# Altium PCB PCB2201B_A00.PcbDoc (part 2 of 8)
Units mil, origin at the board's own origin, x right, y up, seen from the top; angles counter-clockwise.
Board outline 4523.63 x 2358.23 mil, 6 copper layers (Top Layer, Signal Layer 2, Signal Layer 3, Signal Layer 4, Signal Layer 5, Bottom Layer), stack 61.221 mil thick; 383 components, 308 nets, 1386 pads, 1147 vias.
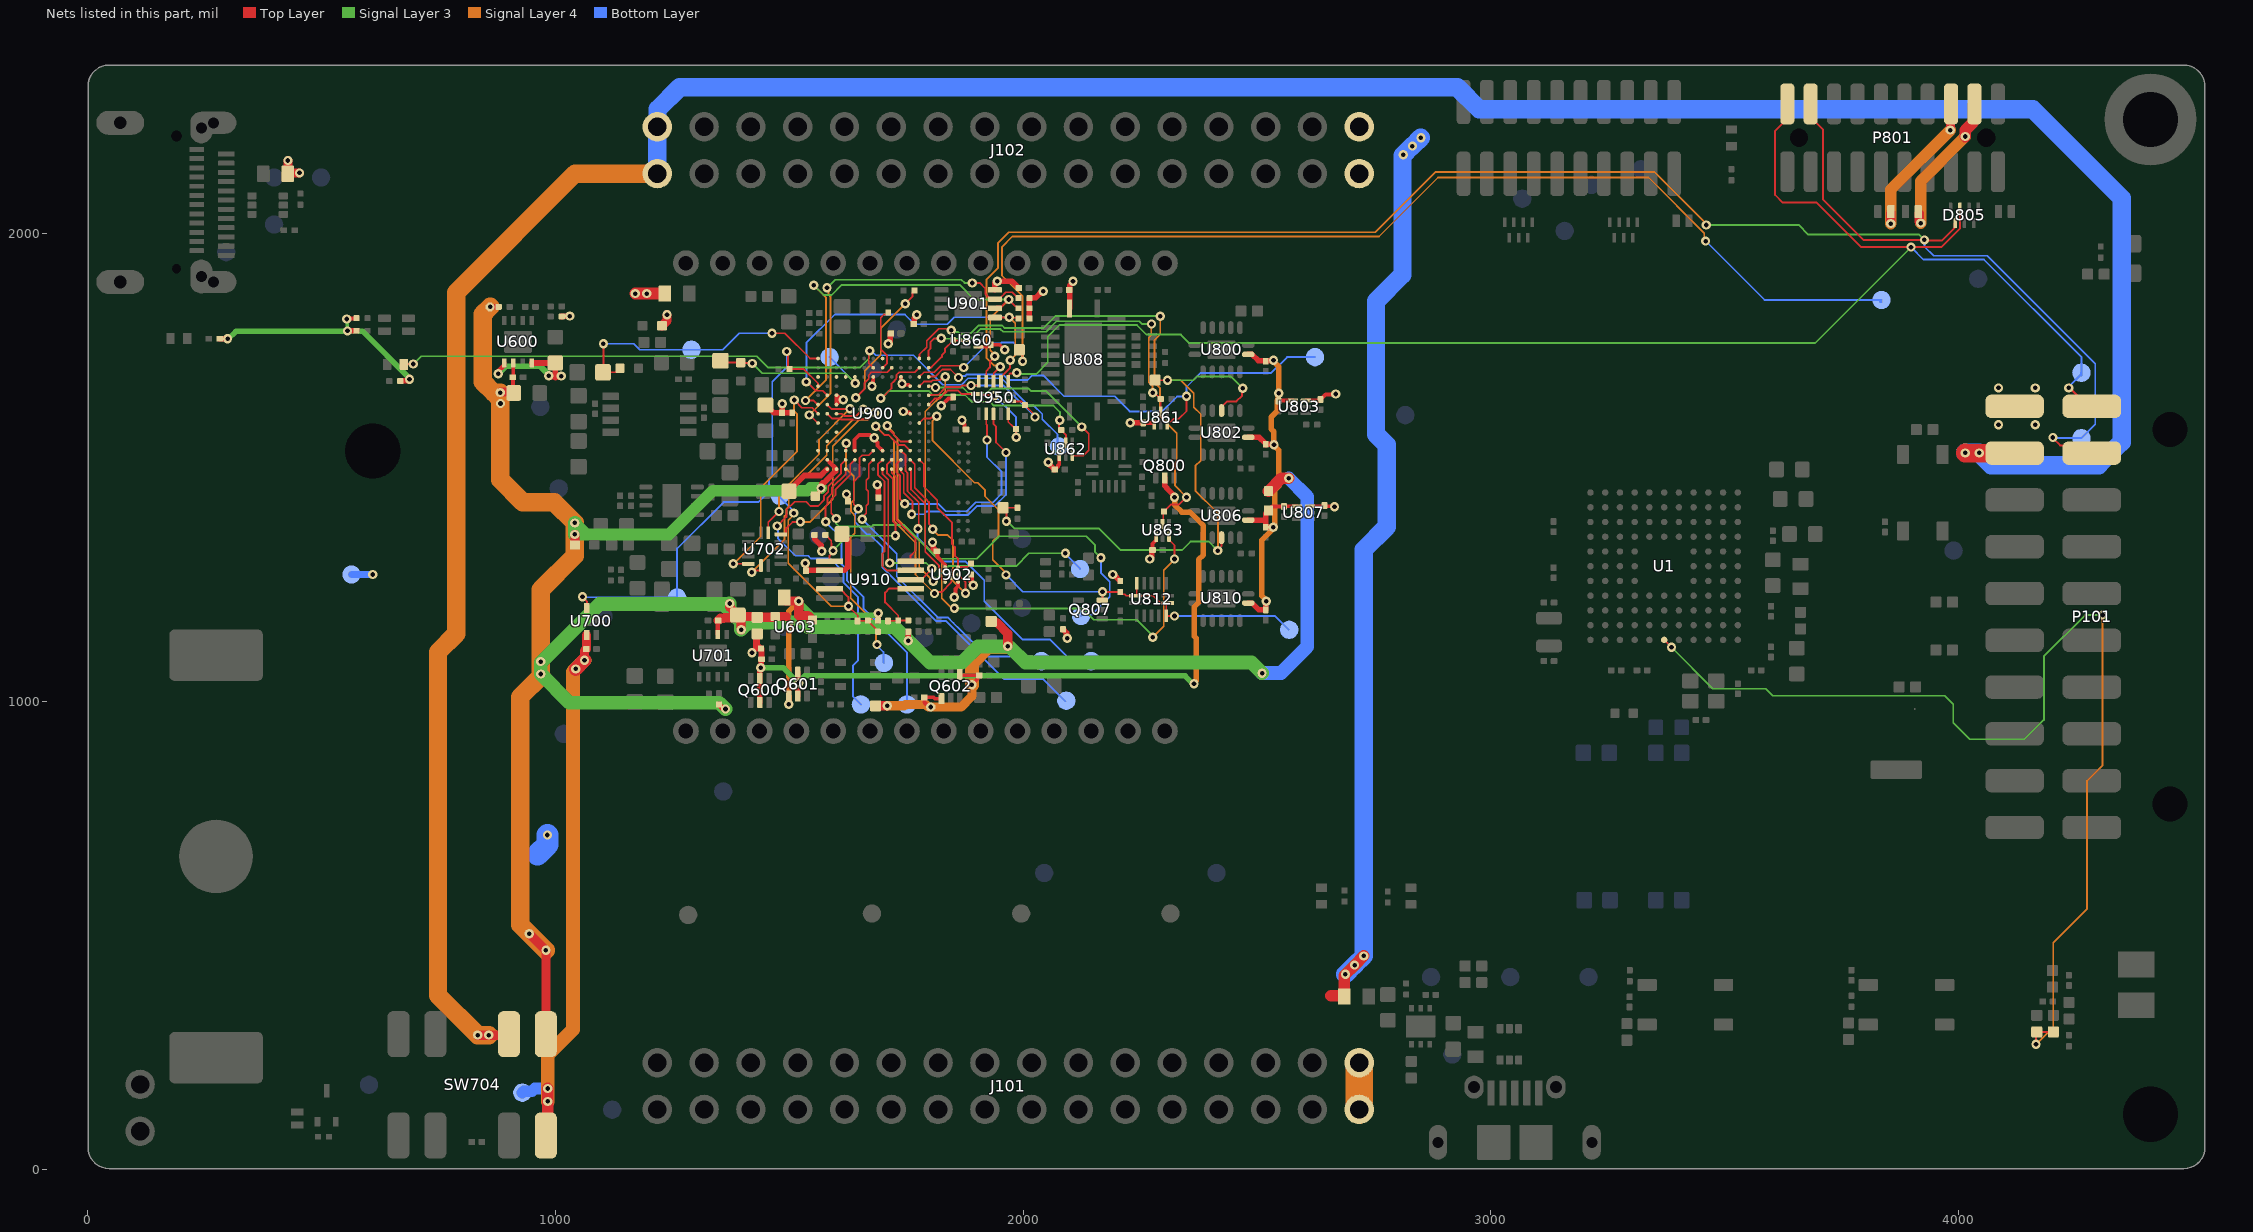
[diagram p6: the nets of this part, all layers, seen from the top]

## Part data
LED100 LED101: library part Yellow

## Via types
v1: diameter 19.68, hole 9.84, Top Layer to Bottom Layer, tented both sides, 768 vias
v2: diameter 20, hole 9.84, Top Layer to Bottom Layer, tented both sides, 379 vias

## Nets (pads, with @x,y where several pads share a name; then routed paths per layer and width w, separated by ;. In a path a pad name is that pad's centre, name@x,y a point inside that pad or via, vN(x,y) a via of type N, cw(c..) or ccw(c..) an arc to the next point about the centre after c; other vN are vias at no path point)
3V3: C607.1 C807.1 C808.1 C860.1 C862.1 C864.1 C866.1 C868.1 C907.1 C908.1 C909.1 C910.1 C911.1 C914.1 C921.1 C922.1 C924.1 C925.1 C926.1 C927.1 C951.1 D807.1 J101.31 J101.32 J102.31 J102.32 L704.1 L900.1 P101.20 P801.3 R601.2 R838.2 R840.2 R903.1 R906.2 R907.1 R908.1 R909.1 R912.1 R919.1 R920.1 R982.1 TPJ600.1 TPJ950.1 U600.1 U600.4 U803.6 U807.6 U808.1 U860.1 U861.1 U862.1 U863.1 U900.C6 U900.C9 U900.G3 U900.H11 U900.J11 U900.K3 U900.L4 U900.L7 U901.8 U902.A1 U902.E3 U910.2 | length 2868.1
  Top Layer w7.87: v1(555.02,1817.7) 555.92,1818.59 574.77,1818.59 R920.1@575.67,1819.49 ; v2@1606.3,1644.69 1606.3,1639.76 U900.H11@1601.38,1634.84 U900.J11@1601.38,1654.53 1603.17,1654.53 1612.54,1645.16 v2(1615.82,1645.16) ; U900.C9@1640.75,1536.42 1640.04,1537.12 1640.04,1559.39 1650.26,1569.6 1673.18,1569.6 1677.82,1564.96 v2@1682.09,1564.96 ; v2(1677.17,1674.21) 1679.49,1676.53 1679.49,1685.11 1680.12,1685.74 U900.L7@1680.12,1693.9 ; v2(1682.09,1563.98) 1682.09,1560.7 1689.15,1553.63 1689.15,1547.07 U900.C6@1699.8,1536.42 ; v2(1712.35,1764.79) v2@1714.67,1767.11 ; U900.L4@1739.17,1693.9 1739.17,1681.84 v2(1741.45,1679.56) ; v2(1744.09,1620.08) 1746.41,1617.76 1756.26,1617.76 U900.G3@1758.86,1615.16 ; v2@1744.09,1679.13 1745.99,1677.24 1755.83,1677.24 U900.K3@1758.86,1674.21 ; C914.1@1816.08,1321.44 1817.09,1320.43 1817.09,1309.03 1833.59,1292.53 1833.59,1287.48 U902.A1@1833.66,1287.4 ; v2(1825.03,1632.09) 1840.77,1647.83 1848.45,1647.83 1850.82,1650.2 C911.1@1850.82,1650.98 ; v2(1853.33,1223.18) 1855.67,1223.18 1855.67,1240.84 1861.15,1246.32 1861.15,1255.83 U902.E3@1861.22,1255.91 ; v2(1869.52,1600.95) 1869.52,1597.67 1875,1592.19 1875,1584.09 1877.36,1581.73 C909.1@1878.15,1581.73 ; U860.1@1904.49,1758.23 1927.32,1758.23 1931.1,1762.01 C862.1@1931.1,1762.8 1950.37,1762.8 1960.83,1752.34 v2(1961.04,1752.34) ; C860.1@2067.91,1496.06 2068.7,1496.06 2074.61,1501.97 2074.61,1504.7 2077.76,1507.85 U862.1@2077.76,1525.59 ; C864.1@2256.89,1595.47 2280.51,1595.47 U861.1@2280.51,1592.52 ; C866.1@2276.57,1323.82 2276.57,1337.6 2284.45,1345.47 U863.1@2284.45,1352.36 ; U803.6@2604.33,1643.7 2633.86,1643.7 C807.1@2635.83,1645.67 2635.83,1646.46 2638.19,1648.82 2638.98,1648.82 2646.65,1656.5 2667.32,1656.5 v1(2668.31,1657.48) ; U807.6@2613.38,1417.7 2642.76,1417.7 C868.1@2644.17,1419.1 2645.41,1417.86 2664.38,1417.86 v1(2665.63,1416.61)
  Top Layer w10: v1(878.46,1700.72) 880.31,1702.57 880.31,1707.99 891.2,1718.87 U600.1@891.2,1723.64
  Top Layer w11.81: C907.1@1449.8,1629.92 1454.72,1629.92 1467.52,1617.13 C924.1@1485.24,1617.13 ; v2(1485.24,1636.81) C924.1@1485.24,1617.13 ; C925.1@1506.89,1617.13 C924.1@1485.24,1617.13 ; v2(1535,1295.63) 1536.02,1294.61 1536.02,1279.92 C922.1@1536.42,1279.53 ; C922.1@1536.42,1280.12 1536.81,1280.51 1618.08,1280.51 1625,1287.43 1625,1345.47 C921.1@1614.17,1356.3 ; R982.1@1553.98,1356.38 1554.37,1356.38 1554.76,1355.98 1554.76,1347.68 1568.38,1334.06 1568.38,1322.89 v2(1569.95,1321.32) ; v2(1688.55,1463.74) 1688.27,1463.74 1688.27,1463.06 1690.55,1460.78 C926.1@1690.55,1435.16 ; v2@1712.6,1764.79 v2(1712.35,1764.79) 1712.35,1767.01 1716.42,1771.07 1716.42,1786.14 1716.81,1786.54 C910.1@1717.6,1786.54 ; C908.1@1767.28,1807.09 1767.68,1807.48 1767.68,1819.32 1772.72,1824.36 v2(1772.72,1826.57) ; v2(1806.53,1340.55) 1806.1,1340.55 1806.1,1338.34 v2@1807.87,1336.56 ; R906.2@1888.75,1271.56 1889.14,1271.17 1889.14,1255.96 1893.8,1251.29 v2(1893.8,1249.08) ; U901.8@1939.96,1879.92 1939.96,1893.7 v2(1944.88,1898.62) 1976.38,1898.62 C951.1@1991.14,1883.86 ; R908.1@2013.78,1818.9 R907.1@2013.78,1840.55 R909.1@2013.78,1862.2 2014.17,1862.6 2026.72,1862.6 2041.09,1876.97 v2(2043.31,1876.97) ; v2(2054.13,1511.81) 2055.7,1510.24 2055.7,1506.31 2057.2,1504.81 2058.38,1504.81 2067.13,1496.06 C860.1@2067.91,1496.06 ; R838.2@2085.63,1154.53 2086.02,1154.13 2086.02,1153.74 2092.92,1146.84 2092.92,1137.39 v2(2094.49,1135.83) ; U808.1@2099.41,1840.35 2099.41,1878.94 C808.1@2098.43,1879.92 2099.21,1879.92 2099.61,1880.32 2099.61,1889.29 2106.72,1896.41 v2(2106.72,1898.62) ; v2(2191.93,1271.65) 2193.5,1270.09 2195.86,1270.09 2207.68,1258.27 R840.2@2207.68,1257.87 ; v2(2228.95,1595.93) 2229.18,1595.7 2256.66,1595.7 C864.1@2256.89,1595.47 ; v2(2270.67,1304.84) 2270.67,1305.37 2275.39,1310.09 2275.39,1323.43 2275.79,1323.82 C866.1@2276.57,1323.82
  Top Layer w12: R903.1@283.46,1775.59 v1(300.2,1775.59) ; v1(556.42,1792.17) 556.61,1792.36 575.47,1792.36 R919.1@575.67,1792.56 ; R912.1@669.29,1685.04 669.59,1685.34 683.26,1685.34 686.9,1688.98 v1(688.98,1688.98) ; U600.4@950.26,1723.64 995.29,1723.64 C607.1@996.06,1724.41 ; v1(986.47,1696.4) 987.94,1694.93 998.69,1694.93 1000.45,1693.17 ; C607.1@999.47,1723.64 C607.1@1000.45,1723.64 ; 1000.98,1692.64 1000.45,1693.17 ; C607.1@1001.44,1723.64 C607.1@1000.45,1723.64 ; v1(1013.4,1695.69) 1011.93,1694.22 1001.51,1694.22 1000.45,1693.17 ; R601.2@1014.23,1823.05 1014.53,1823.35 1031.02,1823.35 v1(1031.5,1823.82) ; v2(1622.84,1443.25) 1622.84,1441.09 1625.69,1438.25 1625.69,1428.45 C927.1@1625.98,1428.15 ; v2(1806.53,1340.55) 1808.06,1339.02 1808.06,1328.67 1815.29,1321.44 C914.1@1816.08,1321.44 ; 1000.45,1693.17 C607.1@1000.45,1723.64
  Top Layer w19.68: L704.1@1228.35,1803.15 1239.17,1813.98 v2(1239.17,1826.77) ; D807.1@3915.35,2043.31 3915.35,2025.59 v1(3918.31,2022.64)
  Top Layer w25: v2(1171.26,1872.05) v2(1195.87,1872.05) L900.1@1234.65,1872.05 ; v2(4013.78,2207.68) 4013.78,2221.22 4030.77,2238.21 4030.77,2274.72 P801.3@4033.27,2277.22
  Signal Layer 3 w4: J101.32@2718.5,225.39 J101.32@2722.44,229.33
  Signal Layer 3 w7.87: v1(555.02,1817.7) 555.72,1817 555.72,1792.86 v1(556.42,1792.17)
  Signal Layer 3 w12: v1@300.2,1773.62 300.31,1773.62 318.02,1791.34 556.42,1791.34 562.97,1791.34 562.57,1791.75 588.16,1791.75 690.93,1688.98 v1@691.93,1688.98 ; v1(878.46,1700.72) 894.48,1716.73 968.22,1716.73 986.47,1698.48 v1(986.47,1696.4)
  Signal Layer 4 w25: v1(3918.31,2022.64) 3918.31,2112.2 v2(4013.78,2207.68)
  Signal Layer 4 w59.06: J101.31@2718.5,128.43 J101.32@2718.5,225.39
  Bottom Layer w15.75: TPJ600.1@564.95,1271.71 610.18,1271.71 v1(610.24,1271.65)
  Bottom Layer w47.24: TPJ950.1@962.55,673.21 983.62,694.28 v1(983.62,715.04)
  other v1: 4084.54,1591.73 4163.28,1591.73 4084.54,1670.47 4163.28,1670.47
3V6_SW: C608.1 L702.1 Q601.1 R639.2 U603.B1 | length 565.5
  Top Layer w7.87: U603.B1@1520.67,1167.32 1520.67,1184.06
  Top Layer w11.81: Q601.1@1499.02,1011.81 v2(1499.09,994.64) v2(1499.09,994.64) ; R639.2@1689.96,1173.23 1690.35,1173.62 1690.35,1185.19 1691.73,1186.56 1690.29,1187.99 v2(1690.84,1188.54)
  Top Layer w19.68: L702.1@1489.76,1222.44 1489.76,1218.31 1493.11,1214.96 1520.19,1214.96 1520.58,1214.57 v2(1520.67,1214.57) 1520.67,1184.06 1540.35,1184.06 C608.1@1550.2,1174.21
  Signal Layer 3 w11.81: v2(1520.67,1214.57) 1550.9,1184.33 1685.07,1184.33 1689.51,1188.77 1690.29,1187.99 v2(1690.84,1188.54)
  Signal Layer 4 w11.81: v2(1499.09,994.64) 1499.09,1192.99 v2(1520.67,1214.57)
3V6_SW_SENSE: C641.1 R639.1 R640.2 TP923.1 U910.4 | length 490.3
  Top Layer w3.94: U910.4@1586.61,1241.14 1609.25,1241.14 1626.97,1223.43 v2(1626.97,1203.74) 1646.65,1184.06 C641.1@1646.65,1172.24 1647.15,1172.74 1667.82,1172.74 R640.2@1668.31,1173.23 1668.31,1172.83 1685.63,1155.51 1685.63,1153.94 R639.1@1689.96,1149.61
  Signal Layer 4 w3.94: v1(1509.84,1403) 1509.84,1398.83 1498.31,1387.3 1498.31,1295.98 1590.55,1203.74 v2(1626.97,1203.74)
  Bottom Layer w3.94: TP923.1@1480.31,1439.96 1480.31,1436.52 1510.83,1406 1510.83,1405.51 1510.83,1403.98 v1(1509.84,1403)
5V: C600.1 C609.1 C611.1 C673.1 C674.1 C702.1 C703.1 C901.1 D806.1 L402.1 L600.2 L700.1 L800.1 P801.5 Q602.1 Q602.4 R600.2 R622.2 R633.2 R681.2 R690.2 R700.2 SW704.8 U600.2 U603.A2 U603.B2 U701.2 U900.A11 U900.B12 | length 8753.4
  Top Layer w7.87: C611.1@909.45,1661.42 911.2,1659.66 C611.1@911.87,1659.66 ; C600.1@909.9,1693.13 909.9,1662.93 C611.1@911.42,1661.42 ; C600.1@910.43,1693.9 910.4,1693.93 910.4,1723.15 U600.2@910.89,1723.64 ; C702.1@1347.44,1172.24 C702.1@1348.43,1173.23 ; 1493.11,1182.09 1500.23,1174.96 1500.23,1172.33 1504.92,1167.64 U603.A2@1504.92,1151.57 ; C901.1@1556.1,1438.98 1565.96,1448.84 1565.96,1454.1 v2(1568.28,1456.42) ; U900.B12@1581.69,1516.73 1587.6,1510.83 1587.6,1509.84 ; C674.1@1791.57,1006.77 C674.1@1789.21,1009.13 ; v1(1802.68,988.62) 1799.49,988.62 1789.72,998.38 1789.27,998.38 C674.1@1789.21,1009.13 ; Q602.1@1825.4,1006.5 1811.23,1006.5 1808.59,1009.13 C674.1@1789.21,1009.13 C674.1@1789.21,1009.13 ; Q602.4@1865.16,1058.07 1866.97,1056.26 C673.1@1905.67,1056.26 ; v1(1890.75,1035.87) 1903.31,1048.43 1903.31,1053.9 C673.1@1905.67,1056.26 ; C673.1@1906.46,1056.26 C673.1@1905.67,1056.26
  Top Layer w9.84: U701.2@1347.44,1143.7 C702.1@1347.44,1172.24 ; 1587.6,1510.83 1599.41,1499.02 U900.A11@1599.41,1496.06
  Top Layer w11.81: v1(861.22,1843.5) 861.33,1843.61 879.29,1843.61 R600.2@879.39,1843.72 ; R700.2@1350.39,994.09 1350.39,993.7 1358.23,985.86 1362.56,985.86 v2(1364.13,984.3) ; 1581.39,1474.67 1581.59,1474.67 ; U900.A11@1599.41,1495.08 1599.41,1492.49 1581.59,1474.67 ; v2(1754.92,1129.92) R633.2@1754.92,1149.61 ; v2@1569.85,1460.2 1569.85,1465.36 1572.01,1467.52 1574.44,1467.52 1581.59,1474.67 ; v2@1569.85,1460.2 1569.85,1457.98 v2(1568.28,1456.42) 1568.28,1458.63 v2@1569.85,1460.2
  Top Layer w19.68: v1(429.13,2156.5) 429.13,2128.35 L600.2@428.74,2127.95 430.71,2129.92 v1(453.74,2129.92) ; v1(882.87,1660.43) 883.86,1661.42 C611.1@909.45,1661.42 ; v1(944.88,503.94) v1(980.31,468.5) SW704.8@980.31,289.37 SW704.8@980.31,285.43 ; L700.1@1042.32,1334.65 v2(1042.32,1357.28) ; C702.1@1348.43,1173.23 1353.35,1178.15 1360.54,1178.15 1361.52,1179.13 1384.84,1179.13 C703.1@1390.75,1185.04 ; v2(1373.03,1209.65) 1373.09,1209.59 1373.09,1201.71 1389.76,1185.04 C703.1@1390.75,1185.04 ; v2(1397.64,1153.54) 1397.58,1153.6 1397.58,1179.13 C703.1@1394.62,1182.09 ; 1493.11,1182.09 C609.1@1470.47,1182.09 1468.5,1180.12 R622.2@1432.09,1180.12 1430.12,1182.09 C703.1@1394.62,1182.09 ; R681.2@1685.04,991.14 v1(1709.65,991.14) ; R690.2@1932.09,1171.26 1934.06,1169.29 1943.5,1169.29 1967.46,1145.34 1967.46,1118.17 v2(1967.52,1118.11) ; v1(3854.33,2021.65) D806.1@3854.33,2044.54 ; v1(3981.3,2221.46) 3981.92,2222.08 3981.92,2275.88 P801.5@3983.27,2277.22 ; C703.1@1390.75,1185.04 1393.7,1182.09 C703.1@1394.62,1182.09 ; C703.1@1390.75,1185.04 1391.67,1185.04 C703.1@1394.62,1182.09
  Top Layer w25: L800.1@2524.61,1449.8 2552.17,1477.36 v2(2567.91,1477.36) ; 2658.19,371.34 2685.73,371.34 L402.1@2686.42,370.65 ; L402.1@2686.42,370.08 L402.1@2686.42,370.65 ; v1(2728.35,456.69) v1(2708.66,437.01) 2686.42,414.76 L402.1@2686.42,370.65
  Signal Layer 3 w25: v2(1042.32,1357.28) 1066.93,1357.28 ; v2(1042.32,1381.89) 1066.93,1357.28 ; v2(1568.28,1456.42) 1545.33,1456.42 1539.65,1450.73 1337.34,1450.73 1243.9,1357.28 1066.93,1357.28
  Signal Layer 3 w29.53: v2(1042.32,1357.28) v2(1042.32,1381.89) ; v2(1364.13,984.3) 1350.98,997.44 1031.1,997.44 v2(969.49,1059.06) 969.49,1083.66 1094.78,1208.96 1358.85,1208.96 ; v2@1373.03,1208.96 1358.85,1208.96 ; v2(1373.03,1209.65) 1373.03,1194.78 ; v2(1967.52,1118.11) 1903.54,1118.11 1869.09,1083.66 1801.18,1083.66 v2(1754.92,1129.92) 1725.11,1159.73 1540.71,1159.73 1531.15,1169.29 1413.38,1169.29 ; v2@1972.44,1116.14 2004.92,1083.66 2488.19,1083.66 v2(2510.83,1061.02) ; 1358.85,1208.96 1373.03,1194.78 ; 1373.03,1194.78 1397.64,1170.17 1397.64,1169.29 ; 1397.64,1169.29 1413.38,1169.29 ; 1397.64,1169.29 v2(1397.64,1153.54) 1413.38,1169.29
  Signal Layer 4 w19.68: v1(1709.65,991.14) 1746.2,991.14 1749.09,994.03 1792.4,994.03 1797.81,988.62 v1(1802.68,988.62) 1867.71,988.62 1890.75,1011.65 v1(1890.75,1035.87)
  Signal Layer 4 w25: v1(3854.33,2021.65) 3854.33,2094.49 v1(3981.3,2221.46)
  Signal Layer 4 w29.53: v1(1890.75,1035.87) 1890.75,1081.81 1925.08,1116.14 1965.55,1116.14 v2(1967.52,1118.11)
  Signal Layer 4 w39.37: v1(861.22,1843.5) 845.43,1827.72 845.43,1683.5 868.5,1660.43 ; v2(969.49,1059.06) v2(969.49,1085.63) 969.49,1239.17 1042.32,1312.01 v2(1042.32,1357.28) ; v2@970.47,1055.12 925.2,1009.84 925.2,523.62 v1(980.31,468.5) ; v2@1042.32,1358.27 v2(1042.32,1381.89) 998.03,1426.18 931.1,1426.18 882.87,1474.41 v1@882.87,1646.05 ; 868.5,1660.43 v1(882.87,1660.43) v1@882.87,1646.05 ; 868.5,1660.43 v1@882.87,1646.05
  Bottom Layer w29.53: v2(2510.83,1061.02) 2551.18,1061.02 2607.28,1117.13 2607.28,1437.99 v2(2567.91,1477.36)
  Bottom Layer w39.37: v1(2688.98,417.32) v1(2708.66,437.01) v1(2728.35,456.69) 2728.35,1324.78 2777.12,1373.55 2777.12,1548.55 2754.37,1571.3 2754.37,1855.79 2811.02,1912.44 2811.02,2167.12 v1(2812.74,2168.84) 2831.02,2187.11 v1(2832.02,2187.11) 2849.93,2205.02 v1(2850.37,2205.02)
  other v1: 883.43,1637.09
5V_DH_SW: C803.1 C805.1 C809.1 C827.1 C869.1 C870.1 L800.2 U800.14 U802.14 U803.1 U806.14 U807.1 U810.14 | length 940.9
  Top Layer w7.87: L800.2@2524.61,1408.46 2524.61,1409.45 2532.29,1417.14 C870.1@2557.66,1417.14 2558.22,1417.7 U807.1@2585.82,1417.7 ; C869.1@2545.77,1642.53 C869.1@2546.75,1643.51 ; v1(2546.72,1658.95) 2546.24,1658.48 2546.24,1644.01 C869.1@2546.75,1643.51 ; U803.1@2576.77,1643.7 2546.94,1643.7 C869.1@2546.75,1643.51
  Top Layer w11.81: U810.14@2481.3,1210.63 2489.17,1210.63 2503.94,1195.87 C827.1@2518.7,1195.87 2519.09,1196.26 2519.09,1214.2 v2(2519.57,1214.68) ; U806.14@2481.3,1387.8 2518.7,1387.8 ; U802.14@2481.3,1564.96 2486.42,1564.96 2487.2,1564.96 2504.72,1564.96 2518.31,1551.38 2518.31,1550.59 C805.1@2518.7,1550.2 2518.7,1549.41 2519,1549.7 2535.93,1549.7 v2(2536.42,1549.21) ; U800.14@2481.3,1742.13 2489.17,1742.13 2502.76,1728.54 2518.31,1728.54 2518.7,1728.15 C803.1@2518.7,1727.9 ; C803.1@2518.7,1727.36 C803.1@2518.7,1727.9 ; L800.2@2524.61,1408.46 2524.61,1407.48 2518.7,1401.57 2518.7,1387.8 ; v2(2534.58,1373.03) C809.1@2518.7,1373.03 2518.7,1387.8 ; v2(2535.32,1729.22) 2534.39,1728.29 2519.09,1728.29 C803.1@2518.7,1727.9
  Signal Layer 4 w11.81: v2(2519.57,1214.68) 2519.57,1216.9 2510.64,1225.83 2510.64,1345.28 2533.02,1367.66 2533.02,1371.46 v2(2534.58,1373.03) ; v2(2535.32,1729.22) 2535.32,1727 2546.72,1715.61 v1(2546.72,1658.95) 2545.21,1657.44 2545.21,1644.9 2543.31,1643 2543.31,1621.11 2529.96,1607.77 2529.96,1582.83 2535.86,1576.93 2535.86,1549.77 v2(2536.42,1549.21) 2536.42,1547 2546.68,1536.73 2546.68,1460.47 2538.39,1452.17 v2@2538.39,1373.03
5V_EXP: J102.1 J102.2 P101.18 SW704.7 | length 6645.5
  Top Layer w20: v1(834.65,287.4) v1(858.27,287.4) 899.61,287.4 SW704.7@901.57,285.43
  Top Layer w39.37: v1(4013.74,1531.5) 4013.74,1531.1 P101.18@4123.91,1531.1
  Signal Layer 4 w39.37: v1(858.27,287.4) v1(834.65,287.4) 749.76,372.28 749.76,1106.06 788.74,1145.04 788.74,1874.37 1042.8,2128.43 J102.1@1218.5,2128.43
  Bottom Layer w39.37: J102.1@1218.5,2128.43 J102.2@1218.5,2228.43 1218.88,2228.8 1218.88,2265.62 1266.25,2312.99 2927.91,2312.99 2975.32,2265.59 4158.07,2265.59 4347.64,2076.02 4347.64,1554.56 4298.63,1505.55 4069.25,1505.55 v1(4043.31,1531.5) v1(4013.74,1531.5)
5V_SENSE: C635.1 R633.1 R634.2 U910.7 | length 173.9
  Top Layer w3.94: C635.1@1711.61,1172.24 1712.11,1172.74 1732.78,1172.74 R634.2@1733.27,1173.23 ; R633.1@1754.92,1173.23 R634.2@1733.27,1173.23 ; U910.7@1759.84,1241.14 1759.03,1241.96 1714.18,1241.96 1705.11,1232.9 1705.11,1212.21 1733.27,1184.06 R634.2@1733.27,1173.23
5V_SW: C610.1 Q600.2 Q600.5 Q601.2 Q601.5 Q800.5 R622.1 R623.2 | length 1708.1
  Top Layer w11.81: Q601.2@1518.7,1011.81 1518.7,1038.39 v2@1518.7,1040.3 ; Q601.5@1518.7,1062.99 v2@1518.7,1040.3 ; v2(1520.61,1040.3) v2@1518.7,1040.3 ; Q800.5@2303.15,1478.35 2303.15,1461.06 2307.48,1456.72 2307.48,1455.56 2323.82,1439.22 v2(2323.82,1437.01)
  Top Layer w12: v2(1420.94,1104.4) 1420.94,1105.22 1429.08,1113.36 ; R622.1@1432.09,1144.69 R622.1@1432.09,1138.16 ; Q600.2@1437.52,998.43 Q600.5@1437.52,1049.61 1437.61,1049.7 1437.61,1068.01 1439.65,1070.04 v2(1439.65,1072.2) 1440.43,1072.99 1440.43,1090.33 1440.73,1090.63 C610.1@1441.22,1090.63 1441.22,1113.07 1440.63,1113.66 R623.2@1440.24,1113.66 ; 1429.08,1113.36 1429.08,1135.16 R622.1@1432.09,1138.16 ; 1429.08,1113.36 1439.94,1113.36 R623.2@1440.24,1113.66 ; R622.1@1432.09,1138.16 1432.09,1121.42 1439.84,1113.66 R623.2@1440.24,1113.66
  Signal Layer 3 w11.81: v2(1439.65,1072.2) 1488.17,1072.2 1520.08,1040.3 v2(1520.61,1040.3) ; v2@1516.83,1038.73 1533.22,1055.12 2346.21,1055.12 2363.22,1038.11 v2(2365.44,1038.11)
  Signal Layer 4 w11.81: v2(2323.82,1437.01) 2323.82,1420.45 2339.49,1404.78 2356.92,1404.78 2385.55,1376.15 2385.55,1313.58 2375.28,1303.31 2375.28,1211.89 2365.58,1202.2 2365.58,1139.93 2369.8,1135.71 2369.8,1044.68 2365.44,1040.32 v2(2365.44,1038.11)
#RESET: R805.2 R809.1 R810.2 U802.4 U806.11 | length 1299.4
  Top Layer w3.94: v2(1964.57,1385.83) 1964.57,1407.48 R810.2@1957.68,1414.37 R809.1@1988.19,1414.37 ; R805.2@2282.48,1687.01 2282.69,1686.8 v2(2308.83,1686.8) ; v2(2416.34,1322.83) 2416.34,1324.69 2424.21,1332.56 U806.11@2424.21,1350.39 ; U802.4@2424.21,1622.05 2424.21,1629.92 2436.02,1641.73 2455.93,1641.73 2468.28,1654.08 2468.28,1668.5 v2(2469.76,1669.98)
  Signal Layer 3 w3.94: v2(1964.57,1385.83) 1966.54,1385.83 1982.52,1369.84 2162.64,1369.84 2208.66,1323.82 2339.79,1323.82 2358.21,1342.24 2396.93,1342.24 v2(2416.34,1322.83) ; v2(2308.83,1686.8) 2363.74,1686.8 2371.55,1694.6 2445.14,1694.6 v2(2469.76,1669.98)
  Signal Layer 4 w3.94: v2(2308.83,1686.8) 2336.93,1686.8 2364.82,1658.91 2364.82,1629.5 2379.64,1614.67 2379.64,1515.16 2368.39,1503.91 2368.39,1451.04 2416.34,1403.09 v2(2416.34,1322.83)
AEM_5V_#ENABLE: U900.L10
AEM_CALIBRATE0: U702.13 U900.G11 | length 538.6
  Top Layer w3.94: v2(1420.28,1276.42) 1424.62,1276.42 1428.52,1280.31 1437.99,1280.31 1439.96,1282.28 U702.13@1439.96,1290.94 ; U900.G11@1601.38,1615.16 1612.5,1615.16 1617.16,1610.49 1643.97,1610.49 v2(1658.56,1625.08)
  Signal Layer 4 w3.94: v2@1424.25,1279.49 1424.25,1280.39 1490.44,1346.58 1490.44,1396.52 1494.2,1400.29 1494.2,1411.67 1499.3,1416.77 1499.3,1445.17 1580.71,1526.57 1580.71,1547.23 v2(1658.56,1625.08)
AEM_CALIBRATE1: U702.5 U900.G12 | length 492.9
  Top Layer w3.94: U702.5@1482.68,1357.28 1491.34,1357.28 1493.31,1359.25 1493.31,1369.51 1507.37,1383.58 1523.82,1383.58 v2(1524.33,1384.09) ; U900.G12@1581.69,1615.16 1591.54,1605.32 1609.24,1605.32 1611.94,1602.62 1668.56,1602.62 v2(1683.07,1617.13)
  Signal Layer 4 w3.94: v2(1524.33,1384.09) 1545.25,1384.09 1593.43,1432.27 1593.43,1545.42 1651.07,1603.07 1669.01,1603.07 v2(1683.07,1617.13)
AEM_CALIBRATE2: U702.6 U900.H12 | length 390.5
  Top Layer w3.94: U702.6@1455.71,1360.63 1455.71,1383.2 1478.43,1405.93 v2(1478.43,1406.39) ; U900.H12@1581.69,1634.84 1591.54,1625 1629.16,1625 v2(1630.12,1625.96)
  Signal Layer 4 w3.94: v2(1478.43,1406.39) 1478.87,1406.84 1478.87,1443.44 1563.98,1528.54 1563.98,1559.82 v2(1630.12,1625.96)
AEM_CALIBRATE3: U702.12 U900.G13 | length 503.3
  Top Layer w3.94: v2(1380.69,1294.72) 1381.46,1294.72 1381.68,1294.51 1412.77,1294.51 U702.12@1412.99,1294.29 ; v2@1511.81,1642.72 1512.79,1642.72 1527.56,1627.95 1549.21,1627.95 U900.G13@1562.01,1615.16
  Signal Layer 4 w3.94: v2(1380.69,1294.72) 1381.46,1294.72 1439.59,1352.86 1439.59,1457.25 1516.73,1534.39 1516.73,1615.16 1510.83,1621.06 v2(1510.83,1644.69)
AEM_CURRENT_HIGH_GAIN: C720.1 R764.2 TP706.1 U900.N13 | length 602.6
  Top Layer w3.94: v2(1103.35,1764.76) 1103.35,1704.72 R764.2@1102.36,1703.74 1129.92,1703.74 C720.1@1138.78,1712.6 ; v2(1463.58,1787.4) 1490.87,1787.4 1545,1733.27 U900.N13@1562.01,1733.27
  Bottom Layer w3.94: v2(1103.35,1764.76) 1168.31,1764.76 1181.1,1751.97 TP706.1@1291.34,1751.97 1358.27,1751.97 1393.7,1787.4 v2(1463.58,1787.4)
AEM_CURRENT_LOW_GAIN: C724.1 R768.2 TP707.1 U900.L9 | length 400.9
  Top Layer w3.94: R768.2@1353.35,1728.35 1357.28,1724.41 1394.68,1724.41 C724.1@1396.65,1724.41 1397.64,1723.43 1421.26,1723.43 v2(1421.26,1722.72) ; U900.L9@1640.75,1693.9 1641.18,1693.47 1641.18,1680.97 v2(1641.6,1680.54)
  Signal Layer 3 w3.94: v2(1421.26,1722.72) 1421.61,1723.07 1442.91,1701.77 1620.37,1701.77 v2(1641.6,1680.54)
  Bottom Layer w3.94: TP707.1@1586.61,1736.22 1586.61,1735.88 1641.6,1680.89 v2(1641.6,1680.54)
AEM_SENSE_SELECT: U900.L13
AEM_SWITCH_POS: U900.L11
AEM_VMCU: C708.1 SW704.4 TP709.1 U700.1 | length 1220.5
  Top Layer w19.68: v2(1062.99,1088.58) 1063.05,1088.64 1063.05,1108.33 C708.1@1066.93,1112.2 U700.1@1066.93,1141.73
  Top Layer w25: SW704.4@980.31,68.9 984.25,72.83 v1(984.25,145.67) v1(984.25,173.23)
  Top Layer w29.53: v2(1044.29,1069.88) v2(1062.99,1088.58)
  Signal Layer 4 w29.53: v1(984.25,145.67) v1(984.25,173.23) 984.25,245.08 1038.39,299.21 1038.39,1063.98 v2(1062.99,1088.58)
  Bottom Layer w25: TP709.1@930.12,164.37 932.87,167.12 950.58,167.12 956.69,173.23 v1(984.25,173.23)
AEM_VMCU_ENABLE: R763.2 TP715.1 U700.4 U900.K13 | length 1010.3
  Top Layer w3.94: v2(1058.6,1223.88) 1067.91,1214.57 U700.4@1067.91,1199.8 ; v2(1495.08,1748.31) 1498.03,1745.36 1498.03,1713.58 R763.2@1500.98,1710.63 1531.36,1710.63 1561.87,1680.12 1561.87,1674.35 U900.K13@1562.01,1674.21
  Bottom Layer w3.94: v2@1064.96,1222.1 1066.02,1223.16 1260.11,1223.16 TP715.1@1260.83,1222.44 1260.83,1327.26 1360.1,1426.54 1434.19,1426.54 1456.21,1448.56 cw(c1480.31,1439.96) 1456.83,1450.12 1456.83,1475.27 1464.09,1482.54 1464.09,1683.58 1495.08,1714.57 v2(1495.08,1748.31)
BC_ADC_SPI_CIPO: U900.B6 U910.9 | length 303
  Top Layer w3.94: U900.B6@1699.8,1516.73 1689.96,1506.89 1689.96,1484.59 1704.02,1470.54 1704.02,1320.83 1699.38,1316.19 1699.38,1289.85 1708.72,1280.51 U910.9@1759.84,1280.51
BC_ADC_SPI_COPI: U900.A6 U910.8 | length 357.8
  Top Layer w3.94: U900.A6@1699.8,1497.05 1699.8,1485.89 1711.89,1473.8 1711.89,1299.21 v2(1714.85,1296.26) ; U910.8@1759.84,1260.83 1782.48,1260.83 1805.12,1283.46 v2(1805.12,1284.45)
  Signal Layer 3 w3.94: v2(1714.85,1296.26) 1793.31,1296.26 v2(1805.12,1284.45)
BC_ADC_SPI_CS: R982.2 U900.B5 U910.1 | length 386.8
  Top Layer w3.94: R982.2@1577.6,1356.38 1577.99,1356.38 1590.24,1344.13 1590.24,1337.95 1590.8,1337.39 1590.8,1325.29 v2(1593.87,1322.21) 1593.87,1319.26 1590.55,1315.94 1586.61,1312.01 U910.1@1586.61,1300.2 ; U900.B5@1719.49,1516.73 1709.65,1506.89 1709.65,1487.8 1721.46,1475.99 1721.46,1385.52 1727.36,1379.61 v2(1727.36,1354.33)
  Signal Layer 3 w3.94: v2(1593.87,1322.21) 1593.87,1322.28 1625.92,1354.33 v2(1727.36,1354.33)
BC_ADC_SPI_SCLK: U900.A5 U910.10 | length 222.2
  Top Layer w3.94: U900.A5@1719.49,1497.05 1719.49,1489.09 1729.33,1479.25 1729.33,1388.78 1770.23,1347.88 1770.23,1322.4 1759.84,1312.01 U910.10@1759.84,1300.2
BC_BUTTON_ENABLE: R981.1 U900.H1 U950.6 U950.12 | length 323.6
  Top Layer w3.94: U900.H1@1798.23,1634.84 1810.95,1647.56 1822.31,1647.56 1834.25,1659.51 1834.25,1660.19 1835.48,1661.42 1838.63,1664.57 1861.15,1664.57 1868.23,1657.48 U950.6@1902.17,1657.48 1904.13,1655.51 1937.01,1655.51 v2(1938.98,1653.54) ; U950.12@1968.5,1614.76 1968.5,1597.57 1979.07,1587.01 1980.91,1587.01 R981.1@1985.24,1582.68 v2(1985.24,1564.96)
  Bottom Layer w3.94: v2(1938.98,1653.54) 1985.24,1607.28 v2(1985.24,1564.96)
BC_DAC_OUT: U900.N6
BC_DBG_#RESET: LED903.1 TPJ956.1 U900.M7 | length 1599.8
  Top Layer w3.94: LED903.1@676.73,1720.87 677.32,1721.46 v1(696.85,1721.46) ; v2(1672.78,1750) 1671.26,1750 1670.28,1749.02 1670.28,1723.43 U900.M7@1680.12,1713.58
  Signal Layer 3 w3.94: v1(696.85,1721.46) 713.58,1738.19 840.28,1738.19 1431.1,1738.19 1455.43,1713.86 1650.87,1713.86 1671.26,1734.25 1671.26,1750 v2(1672.78,1750)
  Bottom Layer w3.94: v2(1672.78,1750) 1675.61,1750 1685.45,1740.16 1765.97,1740.16 1828.92,1677.2 1868.67,1677.2 1882.41,1690.94 1954.05,1690.94 2012.26,1632.73 2023.01,1632.73 2041.06,1614.67 2041.06,1603.83 2074.02,1570.87 2074.02,1548.03 TPJ956.1@2076.77,1545.28
BC_DBG_TCK_SWCLK: TPJ954.1 U900.C10 | length 526.2
  Top Layer w3.94: U900.C10@1621.06,1536.42 1621.56,1536.91 1621.56,1546.75 v2@1621.06,1547.24
  Signal Layer 4 w3.94: v2(1622.05,1552.17) 1622.05,1497.89 1638.31,1481.62 1638.31,1430.72 1632.53,1424.94 1632.53,1406 1638.31,1400.22 1638.31,1399.31 1640.47,1397.16 1640.47,1360.02 1631.89,1351.44 1631.89,1220.69 1685.96,1166.62 1685.96,1129.32 1688.09,1127.19 1688.09,1122.13 v1(1687.92,1121.96)
  Bottom Layer w3.94: v1(1687.92,1121.96) 1687.92,1119.86 1701.83,1105.96 1701.83,1083.61 TPJ954.1@1702.76,1082.68
BC_DBG_TDO_SWO: TPJ955.1 U900.A10 | length 603.8
  Top Layer w3.94: v2(1578.08,1384.38) 1578.08,1417.34 1582.41,1421.67 1582.41,1435.57 1591.63,1444.78 1591.63,1456.87 ; 1598.85,1464.09 1591.63,1456.87 ; U900.A10@1621.06,1497.05 1621.06,1486.31 1591.63,1456.87
  Bottom Layer w3.94: v2@1579.72,1385.83 1579.72,1382.73 1612.2,1350.25 1612.2,1293.31 1624.02,1281.5 1624.02,1258.18 1625,1257.2 1659.45,1222.75 1659.45,1198.06 1751.97,1105.54 TPJ955.1@1751.97,994.09
BC_DBG_TMS_SWDIO: TPJ953.1 U900.B10 | length 748
  Top Layer w3.94: v2(1474.97,1375.28) 1494.34,1394.65 1494.34,1409.7 1511.81,1427.17 1536.42,1427.17 1545.55,1418.03 1562.04,1418.03 1574.54,1430.53 1574.54,1438.83 1583.75,1448.05 1583.75,1460.13 1611.22,1487.6 1611.22,1506.89 U900.B10@1621.06,1516.73
  Bottom Layer w3.94: v2(1474.97,1375.28) 1476.2,1374.05 1476.2,1349.24 1513.76,1311.68 1540.83,1311.68 1546.65,1305.85 1587.85,1305.85 1616.14,1277.56 1616.14,1253.94 ; 1617.13,1253.94 1647.64,1223.43 1647.64,1088.58 1636.81,1077.76 1636.81,1010.83 TPJ953.1@1653.54,994.09
BC_DISP_COM: U900.E11
BC_DISP_PWR_ENABLE: U900.D12
BC_DISP_SPI_COPI: U900.B8
BC_DISP_SPI_CS: U900.C12
BC_DISP_SPI_SCLK: U900.C13
BC_I2C_EXP_ENABLE: R950.1 U900.J1 U950.5 U950.13 | length 358.9
  Top Layer w3.94: U900.J1@1798.23,1654.53 1798.98,1655.28 1807.53,1655.28 1808.04,1655.79 1819.4,1655.79 1826.38,1662.77 1826.38,1663.45 1835.37,1672.44 1866.34,1672.44 1869.37,1675.48 1903.54,1675.48 1905.51,1677.44 U950.5@1905.51,1684.45 ; U950.13@1971.85,1641.73 1996.46,1641.73 2003.94,1634.25 2003.94,1633.46 2025.59,1611.81 v2(2025.59,1608.27)
  Bottom Layer w3.94: v2(1888.82,1675.48) 1958.38,1675.48 v2(2025.59,1608.27)
BC_I2C_EXP_SCL: D805.5 P101.17 P801.17 TPJ651.1 U950.3 | length 3792.7
  Top Layer w3.94: U950.3@1937.01,1684.45 1937.51,1684.95 1937.51,1701.29 1951.51,1715.29 v2(1951.51,1715.82) ; P801.17@3682.09,2276.57 3682.09,2249.91 3709.65,2222.35 3709.65,2072.83 3795.82,1986.66 v1(3926.18,1986.66) ; v1@3929.19,1985.18 3963.52,1985.18 3990.35,2012.01 3990.35,2021.26 D805.5@3992.13,2023.03 ; v1(4200.79,1564.52) 4200.79,1563.06 4216.22,1547.63 4224.25,1547.63 4232.68,1539.2 4232.68,1531.1 P101.17@4273.91,1531.1
  Signal Layer 3 w3.94: v1(3460.04,2018.62) 3657.67,2018.62 3678.26,1998.03 3914.81,1998.03 v1@3924.94,1987.9
  Signal Layer 4 w3.94: v2(1951.51,1715.82) 1948.7,1718.62 1937.65,1718.62 1922.05,1734.23 1922.05,1902.28 1946.85,1927.08 1946.85,1980.31 1969.71,2003.17 2753.17,2003.17 2881.89,2131.89 3349.41,2131.89 3460.04,2021.26 v1(3460.04,2018.62)
  Bottom Layer w3.94: v1(3926.18,1986.66) 3926.49,1986.66 3926.49,1972.44 3946.17,1952.76 4060.43,1952.76 4291.34,1721.85 4291.34,1592.6 TPJ651.1@4261.75,1563.01 ; v1(4200.79,1564.52) 4202.27,1563.04 TPJ651.1@4261.7,1563.04
BC_I2C_EXP_SDA: D805.3 P101.19 P801.19 TPJ650.1 U950.1 | length 3476
  Top Layer w3.94: U950.1@1968.5,1684.45 1970.47,1686.42 1970.47,1699.27 1972.78,1701.58 1985.04,1701.58 v2(1986.22,1702.76) ; P801.19@3633.27,2277.22 3633.27,2245.94 3607.28,2219.96 3607.28,2082.68 3623.46,2066.5 3696.3,2066.5 3791.45,1971.35 v1(3897.64,1971.35) 3897.64,1971.46 3919.73,1971.46 3919.84,1971.35 3932.52,1971.35 3932.63,1971.46 3962.64,1971.46 4001.97,2010.79 D805.3@4001.97,2055.71
  Top Layer w5: P101.19@4234.54,1630.8 4235.63,1631.89 P101.19@4236.42,1631.1 ; v1@4236.22,1677.17 4236.22,1670.83 4275.95,1631.1 4310.88,1631.1 P101.19@4313.28,1633.5
  Signal Layer 3 w3.94: v2@1986.22,1706.69 1992.83,1700.08 2028.06,1700.08 2052.88,1724.9 2052.88,1779.91 2077.81,1804.84 2243.39,1804.84 2263.92,1784.31 2337.52,1784.31 2355.64,1766.19 3692.48,1766.19 v1(3897.64,1971.35)
  Bottom Layer w3.94: v1(3897.64,1971.35) v1(3897.64,1971.35) 3924.21,1944.88 4053.5,1944.88 4261.75,1736.63 TPJ650.1@4261.75,1702.81
  Bottom Layer w5: v1(4234.54,1670.47) 4234.54,1673.03 TPJ650.1@4261.75,1700.25 ; TPJ650.1@4261.75,1697.69 TPJ650.1@4261.75,1700.25 ; TPJ650.1@4261.75,1702.81 TPJ650.1@4261.75,1700.25
BC_SPI_CIPO: U900.B3 U902.C3 | length 392.9
  Top Layer w3.94: U900.B3@1758.86,1516.73 1768.7,1506.89 1768.7,1456.63 1792.95,1432.39 1798.93,1426.4 1798.93,1380.61 1807.09,1372.46 v2(1807.09,1368.11) ; U902.C3@1861.22,1271.65 1876.97,1255.91 v2(1876.97,1231.3)
  Signal Layer 4 w3.94: v2(1807.09,1368.11) 1819.18,1356.02 1839.08,1356.02 1850.67,1344.43 1850.67,1257.59 v2(1876.97,1231.3)
BC_SPI_COPI: U900.C3 U902.D2 | length 565.4
  Top Layer w3.94: v2(1685.04,1588.58) 1703.86,1569.76 1713,1569.76 1734.53,1548.23 1747.05,1548.23 U900.C3@1758.86,1536.42 ; v2(1810.8,1231.07) 1813.87,1234.15 1826.1,1234.15 1846.61,1254.66 1846.61,1262.95 U902.D2@1847.44,1263.78
  Signal Layer 4 w3.94: v2(1685.04,1588.58) 1703.41,1570.21 1712.55,1570.21 1724.09,1558.67 1724.09,1386.15 1770.23,1340 1770.23,1271.64 v2(1810.8,1231.07)
BC_SPI_CS: R906.1 U900.B2 U902.A3 | length 294.6
  Top Layer w3.94: U900.B2@1778.54,1516.73 1788.39,1506.89 1788.39,1459.22 1816.81,1430.8 1816.81,1414.71 1848.15,1383.38 1848.15,1336.9 1854.68,1330.36 1854.68,1311.43 1861.22,1304.9 U902.A3@1861.22,1287.4 1881.36,1287.4 1888.75,1294.79 R906.1@1888.75,1295.19
BC_SPI_SCLK: U900.A3 U902.E1 | length 272.1
  Top Layer w3.94: U900.A3@1758.86,1497.05 1758.86,1496.43 1760.83,1494.46 1760.83,1453.37 1791.06,1423.14 1791.06,1320.38 1801.8,1309.65 1820.59,1290.86 1820.59,1268.98 U902.E1@1833.66,1255.91
BC_TRACECLK: TPJ957.1 U900.B7 | length 677.2
  Top Layer w3.94: v2(1656.5,1389.76) 1656.5,1394.11 1665.14,1402.75 1665.14,1418.94 1669.3,1423.1 1669.3,1449.71 1664.93,1454.08 1664.93,1473 1665.21,1473.28 1665.21,1473.41 1670.28,1478.47 1670.28,1506.89 U900.B7@1680.12,1516.73
  Bottom Layer w3.94: v2(1656.5,1389.76) 1730.31,1315.95 1730.31,1267.41 1817.6,1180.12 1839.11,1180.12 1851.2,1168.03 1864.88,1154.35 1922.93,1096.3 2020.02,1096.3 2029.74,1086.57 TPJ957.1@2039.33,1086.57
BC_TRACED0: TPJ958.1 U900.C7 | length 818.7
  Top Layer w3.94: v2(1647.99,1412.41) 1638.36,1422.04 1638.36,1470.05 1650.59,1482.28 1650.59,1520.81 1656.36,1526.57 1670.28,1526.57 U900.C7@1680.12,1536.42
  Bottom Layer w3.94: v2(1647.99,1412.41) 1647.99,1408.06 1641.03,1401.1 1641.03,1383.36 1667.38,1357 1673.03,1357 1699.38,1330.65 1699.38,1287.21 1814.34,1172.24 1835.85,1172.24 1959.87,1048.23 2043.31,1048.23 TPJ958.1@2090.55,1000.98
BC_TRACED1: TPJ959.1 U900.C4 | length 705
  Top Layer w3.94: U900.C4@1739.17,1536.42 1749.02,1526.57 1749.02,1492.97 1752.95,1489.03 1752.95,1450.11 1777.2,1425.87 1777.2,1370.7 v2(1775.59,1369.09)
  Bottom Layer w3.94: v2(1775.59,1369.09) 1774.61,1368.11 1774.61,1350.17 1825.57,1299.21 1877.28,1299.21 1917.15,1259.34 1917.15,1214.77 1999.31,1132.6 2058.14,1132.6 2104.17,1086.57 2132.91,1086.57 TPJ959.1@2138.78,1080.71
BC_TRACED2: TPJ960.1 U900.D3 | length 790.1
  Top Layer w3.94: v2(1709.56,1589.31) 1712.64,1586.23 1712.64,1581.61 1738.14,1556.1 U900.D3@1758.86,1556.1
  Signal Layer 3 w3.94: v2@1810.04,1258.86 1840.83,1289.65 1985.2,1289.65 2012.48,1316.93 v1(2090.55,1316.93)
  Signal Layer 4 w3.94: v2(1709.56,1589.31) 1723.8,1575.07 1723.8,1570.09 1731.96,1561.93 1731.96,1389.41 1778.11,1343.26 1778.11,1286.85 v2(1808.07,1256.89)
  Bottom Layer w3.94: v1(2090.55,1316.93) 2090.55,1315.89 2122.01,1284.43 TPJ960.1@2122.01,1283.39
BC_TRACED3: TPJ961.1 U900.B9 | length 985.9
  Top Layer w3.94: v2(1601.07,1391.21) 1601.07,1392.14 1590.29,1402.92 1590.29,1432.31 1599.5,1441.52 1599.5,1453.61 ; 1604.41,1458.52 1599.5,1453.61 ; U900.B9@1640.75,1516.73 1630.91,1506.89 1630.91,1485.01 1599.5,1453.61
  Signal Layer 3 w3.94: v2(1601.07,1391.21) 1600.62,1390.76 1600.62,1380.52 1606.85,1374.3 1676.38,1374.3 1679.76,1377.67 1745.14,1377.67 1817.41,1305.4 1901.03,1305.4 1949.05,1353.42 2135.36,1353.42 2153.69,1335.09 2153.69,1320.17 v1(2166.38,1307.48)
  Bottom Layer w3.94: TPJ961.1@2124.02,1183.07 2126.63,1185.69 2147.3,1185.69 2185.4,1223.79 2185.4,1256.31 2166.38,1275.33 v1(2166.38,1307.48)
BC_UIF_BUTTON0: U900.B4 U950.9 | length 518.4
  Top Layer w3.94: U900.B4@1739.17,1516.73 1729.33,1506.89 1729.33,1490.38 1737.2,1482.51 1737.2,1432.85 v2(1747.43,1422.63) ; U950.9@1921.26,1614.76 1921.26,1592.91 1922.98,1591.2 v2(1922.99,1559.22)
  Bottom Layer w3.94: v2(1747.43,1422.63) 1818.77,1422.63 1834.62,1406.78 1879.67,1406.78 1899.08,1426.18 1936.25,1426.18 1953.74,1443.68 1953.74,1491.9 1922.99,1522.65 v2(1922.99,1559.22)
BC_UIF_BUTTON1: U900.A4 U950.10 | length 516.6
  Top Layer w3.94: U900.A4@1739.17,1497.05 1739.51,1496.71 1739.51,1491.34 1745.08,1485.77 1745.08,1446.85 1759.35,1432.58 1763.78,1428.15 1763.78,1403.54 1764.31,1403.01 v1(1761.89,1400.59) ; U950.10@1937.01,1614.76 1937.01,1592.72 1942.32,1587.4 1942.32,1553.74 v2(1963.58,1532.48)
  Bottom Layer w3.94: v1(1761.89,1400.59) 1763.78,1400.59 1788.39,1400.59 1794.38,1406.58 1823.67,1406.58 1831.36,1398.9 1882.93,1398.9 1902.34,1418.31 1939.51,1418.31 1963.58,1442.38 v2(1963.58,1532.48)
BC_VCOM_CTS: U863.3 U900.K2 | length 1297.3
  Top Layer w3.94: U900.K2@1778.54,1674.21 1788.39,1684.06 1803.91,1684.06 1806.58,1686.73 1821.69,1686.73 1829.31,1694.35 v2(1833.66,1694.35) ; U863.3@2312.01,1352.36 2312.01,1345.47 2323.82,1333.66 v2(2323.82,1304.84)
  Signal Layer 3 w3.94: v2(1853.45,1199.24) 2126.87,1199.24 2151.2,1174.92 2243.49,1174.92 2277.56,1140.85 v2(2277.56,1137.8)
  Signal Layer 4 w3.94: v2(1833.66,1694.35) 1833.66,1662.6 1791.06,1620 1791.06,1333.72 1826.27,1298.51 1826.27,1221.14 1850.8,1196.6 v2(1853.45,1199.24) ; v2(2277.56,1137.8) 2300.69,1160.93 2300.69,1281 2323.82,1304.13 v2(2323.82,1304.84)
BC_VCOM_CTS_DIR: R853.2 U863.5 U900.N2 | length 1091.1
  Top Layer w3.94: U900.N2@1778.54,1733.27 1778.54,1741.82 1794.29,1757.57 1794.29,1771.35 1819.91,1796.96 1838.45,1796.96 1842.11,1793.31 v2(1846.46,1793.31) ; U863.5@2298.23,1379.92 2299.7,1381.4 2299.7,1405.02 R853.2@2301.18,1406.5 2301.57,1406.5 2316.62,1421.54 2333.94,1421.54 v2(2349.41,1437.01)
  Signal Layer 3 w3.94: v2(1846.46,1793.31) 1849.53,1790.23 1860.33,1790.23 1864.76,1785.8 1887.18,1785.8 1905.24,1803.86 1955.06,1803.86 1960.69,1798.23 2043.31,1798.23 2068.9,1823.82 v2(2293.31,1823.82)
  Signal Layer 4 w3.94: v2(2293.31,1823.82) 2293.31,1784.87 2280.79,1772.35 2280.79,1681.83 2293.03,1669.59 2293.03,1609.31 2328.46,1573.88 2328.46,1513.72 2325.08,1510.34 2325.08,1461.33 v2(2349.41,1437.01)
BC_VCOM_ENABLE: Q807.3 R840.1 TP930.1 U812.5 U812.6 U812.12 U812.13 U900.F2 | length 1183.6
  Top Layer w3.94: U900.F2@1778.54,1595.47 1788.39,1605.32 1802.31,1605.32 1804.12,1607.13 1813.07,1607.13 v2(1815.9,1609.97) ; Q807.3@2169.29,1216.54 2169.93,1217.18 v2(2169.93,1234.88) ; v2@2170.28,1234.25 2170.59,1234.57 2207.36,1234.57 R840.1@2207.68,1234.25 2207.68,1233.86 2212.01,1229.53 2217.32,1229.53 2220.47,1226.38 U812.13@2239.76,1226.38 2277.78,1226.38 2292.82,1211.34 2305.39,1211.34 U812.6@2306.1,1210.63 ; U812.13@2241.14,1226.38 2243.11,1228.35 U812.12@2243.11,1253.35 ; U812.6@2309.45,1210.63 U812.6@2306.1,1210.63 ; v2(2323.82,1183.07) 2306.69,1183.07 U812.5@2306.1,1183.66 U812.6@2306.1,1210.63
  Signal Layer 4 w3.94: v2(1815.9,1609.97) 1815.9,1609.26 1806.64,1600 1806.64,1557.44 1896.28,1467.8 1903.49,1467.8 1918.59,1452.7 1918.59,1439.46 1947.56,1410.49 1947.56,1354.67 1935.36,1342.47 1935.36,1302.85 1963.69,1274.52 v2(1963.69,1270.73)
  Bottom Layer w3.94: v2(1963.69,1270.73) 1999.54,1234.88 v2(2169.93,1234.88) ; v2(2323.82,1183.07) 2429.19,1183.07 2538.02,1183.07 TP930.1@2567.55,1153.54
BC_VCOM_RTS: U862.3 U900.K1 | length 467.2
  Top Layer w3.94: U900.K1@1798.23,1674.21 1798.98,1673.46 1810.79,1673.46 v2(1812.99,1671.26) ; U862.3@2105.32,1525.59 2129.16,1525.59 2140.47,1536.9 2140.47,1572.42 v2(2125.86,1587.02)
  Signal Layer 3 w3.94: v2(1812.99,1671.26) 1871.16,1671.26 1882.41,1660.01 1923.56,1660.01 1932.57,1669.01 2011.87,1669.01 2017.21,1663.67 2049.22,1663.67 v2(2125.86,1587.02)
BC_VCOM_RTS_DIR: R852.2 U862.5 U900.M2 | length 601
  Top Layer w3.94: v2(1695.87,1648.62) 1698.06,1648.62 1718.65,1669.22 1718.65,1679.22 1723.49,1684.06 1723.57,1684.06 1728.4,1688.89 1728.4,1689 1729.17,1689.77 1729.26,1690.7 1729.32,1692.4 1729.33,1693.43 1729.33,1697.97 1735.1,1703.74 1768.7,1703.74 U900.M2@1778.54,1713.58 ; v2(2078.84,1601.56) 2076.77,1599.49 2076.77,1584.65 2091.54,1569.88 U862.5@2091.54,1553.15
  Signal Layer 3 w3.94: v2(1695.87,1648.62) 1698.06,1648.62 1713.53,1664.09 1798.29,1664.09 1807.14,1655.23 1876.05,1655.23 1890.28,1641 1929.64,1641 1937.92,1632.73 2065.11,1632.73 2078.84,1619 v2(2078.84,1601.56)
BC_VCOM_RXD: R882.2 TPJ606.1 U900.L2 | length 2639.3
  Top Layer w3.94: U900.L2@1778.54,1693.9 1788.39,1703.74 1810.04,1703.74 1823.99,1717.69 1865.01,1717.69 1868.68,1714.02 v2(1873.03,1714.02) ; R882.2@1992.13,1751.97 1999.02,1745.08 v2(1999.02,1727.36)
  Signal Layer 4 w3.94: v2(1999.02,1727.36) 1999.02,1866.36 1954.72,1910.66 1954.72,1971.46 1977.28,1994.01 2760.75,1994.01 2886.81,2120.08 3336.93,2120.08 3455.67,2001.34 3455.67,1987.25 v1(3458.66,1984.25)
  Bottom Layer w3.94: v2(1873.03,1714.02) 1924.07,1765.05 1951.8,1765.05 1954.55,1767.81 1979.24,1767.81 1999.02,1748.03 v2(1999.02,1727.36) ; v1@3459.65,1983.27 3584.6,1858.31 TPJ606.1@3834.65,1858.31 3830.67,1854.33 TPJ606.1@3834.65,1854.33
BC_VCOM_RXD_DIR: R850.2 U860.5 U900.M1 | length 109.7
  Top Layer w3.94: U900.M1@1798.23,1713.58 1798.98,1714.34 1804.35,1714.34 1826.77,1736.76 1826.77,1740.7 1833.11,1747.03 1833.11,1754.17 1850.67,1771.73 R850.2@1850.67,1772.13 1850.73,1772.07 1876.87,1772.07 U860.5@1876.93,1772.01
BC_VCOM_TXD: TPJ607.1 U861.3 U900.L1 | length 1029
  Top Layer w3.94: U900.L1@1798.23,1693.9 1798.93,1694.6 1812.04,1694.6 1827.25,1709.82 1845.05,1709.82 v2(1862.19,1692.67) ; U861.3@2308.07,1592.52 2308.07,1596.12 2310.04,1598.09 2315.61,1598.09 2322.19,1604.67 2333.24,1604.67 2349.35,1620.78 v2(2349.35,1652.5)
  Bottom Layer w3.94: v2@1862.36,1692.77 1865.34,1695.75 1876.08,1695.75 1879.15,1698.82 1957.31,1698.82 1968.84,1687.29 2009.9,1687.29 2019.86,1697.24 2042.91,1697.24 2087.6,1652.56 2195.64,1652.56 2227.84,1620.36 2297.52,1620.36 2322.83,1645.67 2329.02,1651.85 2348.7,1651.85 v2(2349.35,1652.5) 2349.35,1672.41 2379.42,1702.48 2530.45,1702.48 2564.2,1736.22 TPJ607.1@2624.02,1736.22
BC_VCOM_TXD_DIR: R851.2 U861.5 U900.N1 | length 733.7
  Top Layer w3.94: U900.N1@1798.23,1733.27 1798.23,1750.37 1802.17,1754.31 1802.17,1768.09 1810.29,1776.21 v2(1825.24,1776.21) ; v2(2277.56,1660.43) 2280.28,1660.43 2293.78,1646.93 R851.2@2294.17,1646.93 ; U861.5@2294.29,1620.08 R851.2@2294.29,1645.67
  Signal Layer 3 w3.94: v2@1826.77,1775.59 1888.1,1775.59 1908.5,1795.99 1951.8,1795.99 1957.43,1790.35 2049.21,1790.35 2071.57,1812.71 2248.31,1812.71 2253.94,1807.09 v1(2274.61,1807.09)
  Signal Layer 4 w3.94: v1(2274.61,1807.09) 2273.96,1806.44 2273.96,1782.82 2268.7,1777.56 2268.7,1682.09 2276.76,1674.03 2276.76,1661.24 v2(2277.56,1660.43)
BOARD_ID_SCL: R907.2 U900.H13 U901.6 U950.4 | length 1023.1
  Top Layer w3.94: v2(1535.08,1643.42) 1552.36,1643.42 1560.94,1634.84 U900.H13@1562.01,1634.84 ; U950.4@1921.26,1684.45 1921.26,1706.47 1929.07,1714.28 1929.07,1726.58 1939.96,1737.47 v2(1939.96,1738.19) ; U901.6@1939.96,1840.55 1943.9,1844.49 1954.73,1844.49 v2(1969.53,1859.28) ; v2@1968.79,1859.47 1983.38,1844.88 1985.83,1844.88 R907.2@1990.16,1840.55
  Signal Layer 3 w3.94: v2(1552.74,1890.13) 1573.89,1868.97 1591.19,1868.97 1612.69,1890.47 1864.45,1890.47 1895.64,1859.28 v2(1969.53,1859.28)
  Signal Layer 4 w3.94: v2(1535.08,1643.42) 1578.74,1687.09 1578.74,1864.13 v2(1552.74,1890.13) ; v2(1939.96,1738.19) 1939.96,1740.6 1929.92,1750.64 1929.92,1819.68 v2(1969.53,1859.28)
BOARD_ID_SDA: R908.2 U900.J12 U901.5 U950.2 | length 824.9
  Top Layer w3.94: v2(1536.94,1683.18) 1537.81,1684.05 1557.5,1664.37 1571.85,1664.37 U900.J12@1581.69,1654.53 ; U901.5@1939.96,1820.87 1940.31,1821.22 1968.04,1821.22 v2@1970.51,1818.74 ; U950.2@1952.76,1684.45 1952.76,1693.9 1958.66,1699.8 ; 1958.66,1699.82 1972.44,1713.6 v2(1972.44,1729.33) ; v2(1970.51,1821.57) v2@1970.51,1818.74 ; R908.2@1990.16,1818.9 1988.82,1820.23 1972.01,1820.23 v2@1970.51,1818.74
  Signal Layer 4 w3.94: v2(1970.51,1821.57) 1983.27,1808.82 1983.27,1740.16 v2(1972.44,1729.33)
  Bottom Layer w3.94: v2(1536.94,1683.18) 1536.94,1766.71 1597.51,1827.28 1747.52,1827.28 1768.42,1806.38 1837.66,1806.38 1852.84,1821.57 v2(1970.51,1821.57)
BOARD_ID_WP: R909.2 U900.F13 U901.7 | length 770.9
  Top Layer w3.94: v2(1542.81,1612.48) 1543.93,1612.48 1560.94,1595.47 U900.F13@1562.01,1595.47 ; v2(1891.73,1894.69) 1907.48,1894.69 1919.29,1882.87 1919.29,1872.05 1931.1,1860.24 1948.82,1860.24 1954.06,1865.48 1954.06,1865.69 1963.12,1874.75 1977.22,1874.75 1989.76,1862.2 R909.2@1990.16,1862.2
  Signal Layer 3 w3.94: v2(1581.19,1884.44) 1582.07,1884.44 1599.2,1901.57 1868.11,1901.57 1875,1894.69 v2(1891.73,1894.69)
  Signal Layer 4 w3.94: v2(1542.81,1612.48) 1588.36,1658.04 1588.36,1865.64 1584.26,1869.74 1584.26,1881.37 v2(1581.19,1884.44)
BOARD_VER0: R930.1 U900.M5 | length 399.6
  Top Layer w3.94: v2(1642.72,1649.61) 1660.92,1667.81 1660.92,1680.46 1670.28,1689.82 1670.28,1697.97 1676.04,1703.74 1709.65,1703.74 U900.M5@1719.49,1713.58 ; v2@1746.65,1850.39 v2(1748.03,1850.39) 1764.09,1866.46 1764.09,1874.53 R930.1@1768.23,1878.66
  Signal Layer 4 w3.94: v2(1642.72,1649.61) 1661.7,1668.59 1661.7,1706.97 1695.87,1741.14 1695.87,1798.23 1745.08,1847.44 v2@1745.08,1853.35
BOARD_VER1: R931.1 U900.M6 | length 137.2
  Top Layer w3.94: U900.M6@1699.94,1713.72 1709.65,1723.43 1709.65,1739.17 1695.87,1752.95 1695.87,1820.47 1702.68,1827.28 1707.73,1827.28 R931.1@1711.98,1831.53
DAC_LC_EXCITE: R198.1 R300.1 U1.L6 | length 2276.9
  Top Layer w3.94: U1.L6@3370.06,1131.95 3370.1,1131.91 v1(3385.85,1116.09) ; v1(4164.81,267.72) 4164.81,292.76 R300.1@4166.34,294.29 R198.1@4201.66,294.29
  Signal Layer 3 w3.94: v1(3385.85,1116.09) 3474.3,1027.64 3586.8,1027.64 3601.77,1012.68 3970.01,1012.68 3987.99,994.69 3987.99,954.57 4023.07,919.49 4139.96,919.49 4181.54,961.07 4181.54,1096.89 4269.69,1185.04 v1(4307.09,1185.04)
  Signal Layer 4 w3.94: v1(4164.81,267.72) 4201.66,304.57 4201.66,485.12 4273.91,557.37 4273.91,831.1 4307.09,864.28 v1(4307.09,1185.04)
DBG_VREGO: C902.1 U900.A12 | length 104.4
  Top Layer w4.72: U900.A12@1581.09,1496.44 U900.A12@1582.3,1496.44
  Top Layer w11.81: C902.1@1496.8,1449.56 1498.77,1449.56 1532.48,1483.27 1567.72,1483.27 1580.51,1496.06 U900.A12@1580.71,1496.06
